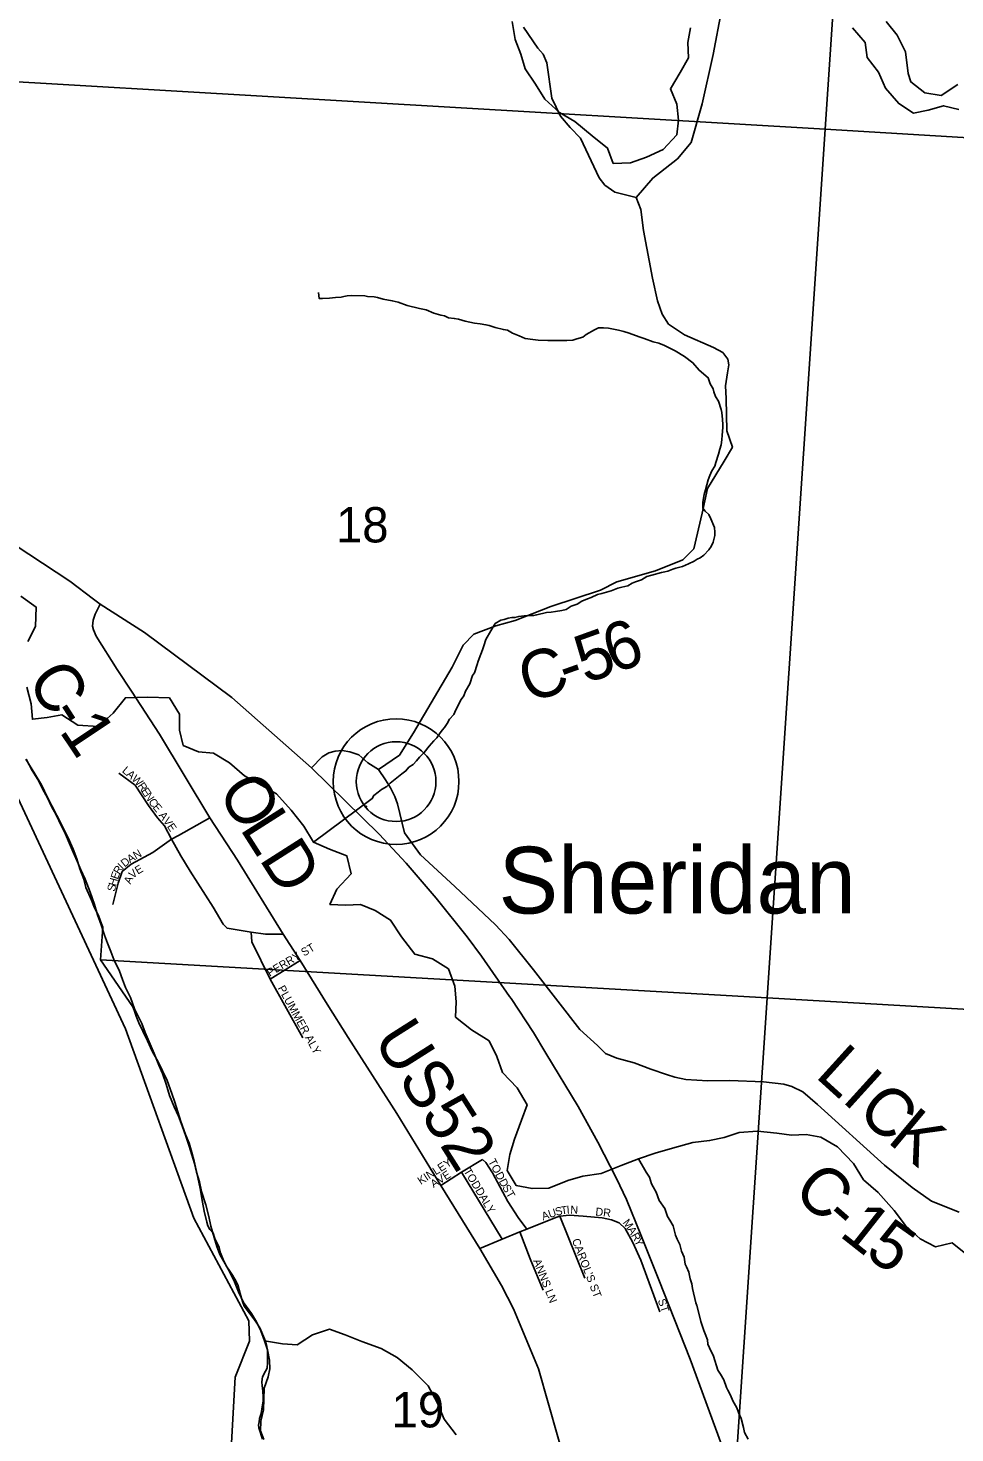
# Model space of a CAD drawing. Extents: x 0 to 34, y 0 to 22.
# Drawn here: x 2.788 to 3.885, y 18.575 to 20.238 of the extents above; entities that cross this region are included whole.
import ezdxf

# ---------------------------------------------------------------- set-up
doc = ezdxf.new("R2010")
doc.units = 0
for name, color, linetype in [('GM_X_County', 7, 'Continuous'), ('GM_X_County_Road', 7, 'Continuous'), ('GM_X_County_Road_Text', 7, 'Continuous'), ('GM_X_Major_River', 7, 'Continuous'), ('GM_X_Minor_River', 7, 'Continuous'), ('GM_X_Section', 7, 'Continuous'), ('GM_X_Section_Text', 7, 'Continuous'), ('GM_X_Township', 7, 'Continuous'), ('GM_X_Township_Road', 7, 'Continuous'), ('GM_X_Township_Subdivision', 7, 'Continuous'), ('GM_X_Township_Subdivision_Text', 7, 'Continuous'), ('GM_X_Unincorporated', 7, 'Continuous'), ('GM_X_Unincorporated_Location', 7, 'Continuous'), ('GM_X_Unincorporated_Text', 7, 'Continuous'), ('GM_X_US_Route', 7, 'Continuous')]:
    doc.layers.add(name, color=color, linetype=linetype)

msp = doc.modelspace()

# ---------------------------------------------------------------- linework, layer by layer
at = {"layer": 'GM_X_County'}
msp.add_lwpolyline([(2.1084, 19.9847), (2.1924, 19.9434), (2.3283, 19.8444), (2.4127, 19.8011), (2.4676, 19.7415), (2.5455, 19.6755), (2.6288, 19.5943), (2.748, 19.3841), (2.9028, 19.0532), (2.9838, 18.8289), (3.0489, 18.7074), (3.0497, 18.6835), (3.0326, 18.641), (3.0273, 18.5491)], dxfattribs=at)
at = {"layer": 'GM_X_County_Road'}
for points in [[(3.2021, 19.3601), (3.2271, 19.377), (3.2437, 19.4034), (3.2893, 19.4814), (3.3023, 19.5074), (3.3153, 19.5204), (3.3413, 19.5302), (3.3641, 19.5367), (3.4064, 19.5529), (3.4649, 19.5724), (3.4845, 19.5822), (3.53, 19.5952), (3.5625, 19.6082), (3.5755, 19.6212), (3.5853, 19.6635), (3.5918, 19.6927), (3.6113, 19.7253), (3.6211, 19.7415), (3.6146, 19.761), (3.6136, 19.7993), (3.613, 19.8141), (3.6155, 19.8295), (3.6171, 19.8393), (3.6158, 19.8459), (3.6099, 19.8537), (3.5989, 19.8597), (3.5643, 19.8748), (3.5454, 19.8874), (3.5379, 19.899), (3.5325, 19.9147), (3.5266, 19.9417), (3.5159, 19.9983), (3.5127, 20.0232), (3.5072, 20.0374), (3.5268, 20.0602), (3.556, 20.083), (3.5723, 20.1025), (3.5853, 20.148), (3.5983, 20.2065), (3.6081, 20.2586)], [(3.8033, 20.2455), (3.8163, 20.2293), (3.826, 20.2098), (3.8293, 20.1838), (3.8325, 20.174), (3.8488, 20.161), (3.8683, 20.1578), (3.8878, 20.1708)], [(2.8728, 19.5558), (2.8669, 19.5439), (2.8644, 19.537), (2.8639, 19.5299), (2.8651, 19.5255), (2.8681, 19.518), (2.8931, 19.4787), (2.9099, 19.453)], [(2.9099, 19.453), (2.9432, 19.4019), (3.0028, 19.303), (3.0355, 19.253), (3.0893, 19.1654), (3.1095, 19.1339), (3.1414, 19.0822), (3.1662, 19.0428), (3.224, 18.953), (3.2762, 18.8678), (3.3224, 18.7932), (3.3479, 18.7494), (3.3619, 18.7216), (3.3918, 18.6508), (3.426, 18.5298)], [(3.1231, 19.362), (3.1354, 19.3753), (3.1433, 19.3797), (3.1509, 19.3819), (3.1592, 19.3827), (3.1685, 19.3812), (3.1788, 19.3775), (3.1898, 19.3682), (3.2021, 19.3601), (3.2107, 19.3479), (3.2163, 19.3385), (3.2215, 19.328), (3.2249, 19.3197), (3.2332, 19.2851), (3.2518, 19.2592), (3.2926, 19.2215), (3.3407, 19.1763), (3.357, 19.1588), (3.3856, 19.123), (3.4405, 19.0523), (3.4616, 19.0335), (3.4708, 19.024), (3.4843, 19.0184), (3.5047, 19.0128), (3.5248, 19.0054), (3.5431, 18.9991), (3.553, 18.996), (3.5661, 18.9934), (3.5921, 18.9916), (3.6182, 18.9921), (3.6578, 18.9904), (3.6819, 18.9878), (3.6916, 18.9849), (3.7046, 18.9786), (3.7219, 18.9638), (3.8012, 18.8917), (3.8339, 18.8655), (3.8568, 18.8491), (3.8896, 18.836)]]:
    msp.add_lwpolyline(points, dxfattribs=at)
at = {"layer": 'GM_X_Major_River'}
for points in [[(2.8856, 19.1447), (2.8815, 19.1546), (2.8781, 19.1641), (2.8739, 19.1762), (2.8698, 19.188), (2.866, 19.2005), (2.8611, 19.2149), (2.855, 19.2305), (2.8501, 19.2415), (2.8456, 19.2517), (2.8407, 19.2623), (2.8361, 19.2733), (2.8316, 19.2836), (2.8267, 19.2938), (2.8206, 19.3063), (2.8153, 19.3162), (2.8104, 19.3268), (2.8044, 19.3371), (2.8002, 19.3465), (2.7923, 19.3591), (2.7851, 19.3723)], [(3.0666, 18.5669), (3.0625, 18.5775), (3.0628, 18.5889), (3.0662, 18.6022), (3.067, 18.628), (3.0715, 18.6413), (3.0738, 18.6507), (3.0731, 18.661), (3.0708, 18.6731), (3.0674, 18.6838), (3.0629, 18.6959), (3.0579, 18.7065), (3.0519, 18.7164), (3.0425, 18.7293), (3.0364, 18.7418), (3.0319, 18.7536), (3.0262, 18.765), (3.0209, 18.7752), (3.0145, 18.7862), (3.0111, 18.7957), (3.0077, 18.8063), (3.0039, 18.8196), (3.0013, 18.831), (2.9979, 18.845), (2.9929, 18.8606), (2.9903, 18.872), (2.9869, 18.8837), (2.9843, 18.8936), (2.9812, 18.9042), (2.9782, 18.9144), (2.9744, 18.9262), (2.9703, 18.9372), (2.9654, 18.9497), (2.9605, 18.9607), (2.9548, 18.9744), (2.951, 18.9877), (2.9465, 19.0002), (2.9423, 19.0101), (2.9366, 19.0241), (2.9321, 19.0351), (2.9261, 19.0487), (2.9223, 19.0594), (2.9136, 19.0768), (2.9087, 19.0901), (2.9026, 19.1022), (2.8992, 19.1117), (2.8955, 19.1216), (2.889, 19.1352), (2.8856, 19.1447)]]:
    msp.add_lwpolyline(points, dxfattribs=at)
at = {"layer": 'GM_X_Minor_River'}
for points in [[(3.3603, 20.2457), (3.364, 20.2244), (3.3708, 20.2069), (3.376, 20.1894), (3.388, 20.1712), (3.3993, 20.1537), (3.4167, 20.1377), (3.4348, 20.127), (3.4552, 20.1102), (3.4733, 20.0957), (3.4801, 20.0775), (3.5005, 20.0782), (3.5195, 20.0849), (3.5392, 20.094), (3.5552, 20.1114), (3.5575, 20.1288), (3.5553, 20.1478), (3.5478, 20.166), (3.5593, 20.185), (3.5692, 20.2024), (3.5685, 20.2206), (3.5716, 20.2381)], [(3.7632, 20.2381), (3.7783, 20.2206), (3.7805, 20.2031), (3.7941, 20.1856), (3.8023, 20.1666), (3.8181, 20.1483), (3.8355, 20.1369), (3.8529, 20.1406), (3.8711, 20.1459), (3.8893, 20.1412)], [(3.5861, 19.6695), (3.5862, 19.6763), (3.5871, 19.6812), (3.5879, 19.6858), (3.5892, 19.6911), (3.5924, 19.7032), (3.5944, 19.7081), (3.5967, 19.7137), (3.6003, 19.719), (3.6015, 19.7235), (3.6047, 19.7333), (3.6063, 19.7394), (3.6079, 19.7443), (3.6088, 19.7504), (3.6092, 19.756), (3.6098, 19.7651), (3.6098, 19.7686), (3.6096, 19.7743), (3.6086, 19.7826), (3.6079, 19.7864), (3.6046, 19.796), (3.6013, 19.8017), (3.5992, 19.8071), (3.5985, 19.8109), (3.5948, 19.8167), (3.5923, 19.8239), (3.5818, 19.8328), (3.5744, 19.8417), (3.5643, 19.8491), (3.5534, 19.8557), (3.5407, 19.862), (3.5339, 19.8648), (3.5275, 19.8664), (3.5169, 19.8704), (3.5109, 19.8724), (3.4989, 19.8768), (3.4925, 19.8784), (3.4864, 19.88), (3.4744, 19.8825), (3.4687, 19.883), (3.4626, 19.8831), (3.458, 19.8805), (3.4481, 19.875), (3.4442, 19.872), (3.437, 19.8698), (3.4321, 19.8684), (3.4252, 19.8678), (3.4188, 19.8679), (3.4025, 19.8678), (3.3912, 19.8683), (3.3851, 19.8692), (3.3757, 19.8705), (3.3689, 19.8733), (3.361, 19.8765), (3.355, 19.88), (3.3501, 19.8808), (3.3403, 19.8833), (3.3331, 19.8857), (3.3294, 19.8865), (3.3226, 19.8877), (3.3158, 19.8886), (3.3048, 19.8907), (3.2969, 19.8931), (3.292, 19.894), (3.2852, 19.8948), (3.2803, 19.8972), (3.2762, 19.898), (3.2679, 19.9001), (3.2585, 19.9044), (3.2509, 19.906), (3.2362, 19.9093), (3.2257, 19.9133), (3.2185, 19.9149), (3.2079, 19.917), (3.2011, 19.919), (3.197, 19.9195), (3.1894, 19.92), (3.186, 19.9208), (3.1705, 19.9211), (3.1652, 19.9208), (3.1614, 19.9201), (3.158, 19.9194), (3.1515, 19.9187), (3.1443, 19.9181), (3.136, 19.9175), (3.1322, 19.9176), (3.1312, 19.9248)], [(3.1254, 19.2742), (3.1949, 19.3257), (3.1968, 19.3294), (3.2018, 19.3335), (3.206, 19.3365), (3.2122, 19.3402), (3.216, 19.3439), (3.2241, 19.3502), (3.2298, 19.3551), (3.2348, 19.3584), (3.2383, 19.3629), (3.2433, 19.3662), (3.2472, 19.3703), (3.2506, 19.3748), (3.2564, 19.3804), (3.2622, 19.3879), (3.2676, 19.3939), (3.2715, 19.3976), (3.2746, 19.4025), (3.2777, 19.4067), (3.2804, 19.41), (3.2835, 19.4145), (3.2863, 19.4198), (3.2913, 19.4254), (3.2937, 19.4307), (3.3003, 19.4431), (3.3034, 19.4472), (3.3054, 19.4529), (3.3105, 19.4615), (3.3137, 19.4714), (3.3157, 19.4747), (3.3192, 19.4845), (3.3204, 19.4883), (3.3232, 19.4966), (3.3252, 19.5019), (3.3268, 19.5064), (3.3292, 19.514), (3.3351, 19.5241), (3.3402, 19.5328), (3.3471, 19.5369), (3.3509, 19.5375), (3.3558, 19.5394), (3.36, 19.54), (3.3638, 19.54), (3.3683, 19.5414), (3.3748, 19.5421), (3.3801, 19.5424), (3.3858, 19.5423), (3.3896, 19.5433), (3.401, 19.5458), (3.4067, 19.5465), (3.4116, 19.5471), (3.4192, 19.5482), (3.4245, 19.5496), (3.4303, 19.5533), (3.4375, 19.5558), (3.4429, 19.5595), (3.4498, 19.5621), (3.454, 19.5639), (3.4616, 19.5672), (3.4665, 19.5686), (3.4776, 19.5715), (3.4856, 19.5747), (3.4902, 19.5758), (3.4974, 19.5776), (3.5027, 19.5809), (3.5066, 19.5824), (3.5134, 19.5845), (3.5199, 19.5886), (3.5256, 19.59), (3.5371, 19.5932), (3.5412, 19.5943), (3.5447, 19.595), (3.5508, 19.5972), (3.5542, 19.5986), (3.5622, 19.6004), (3.5691, 19.6037), (3.5759, 19.6066), (3.5794, 19.6092), (3.5832, 19.6107), (3.5874, 19.614), (3.5932, 19.62), (3.5959, 19.6241), (3.5983, 19.6294), (3.6003, 19.637), (3.6004, 19.6411), (3.6001, 19.6465), (3.5957, 19.6568), (3.5932, 19.6618), (3.5891, 19.666), (3.5861, 19.6695)], [(2.7789, 19.5654), (2.797, 19.5524), (2.7961, 19.5296), (2.787, 19.5115)], [(2.786, 19.4576), (2.7912, 19.4378), (2.7926, 19.4196), (2.8101, 19.4218), (2.8275, 19.4248), (2.8464, 19.4126), (2.8706, 19.411), (2.8881, 19.4268), (2.9026, 19.445), (2.9291, 19.4457), (2.9548, 19.4448), (2.9669, 19.4258), (2.9668, 19.4068), (2.9712, 19.3886), (2.9894, 19.3809), (3.0068, 19.3793), (3.0257, 19.3679), (3.0438, 19.3526), (3.0642, 19.3412), (3.0816, 19.3312), (3.0989, 19.3122), (3.114, 19.2931), (3.1253, 19.2741), (3.1442, 19.2657), (3.1646, 19.258), (3.1698, 19.2368), (3.1531, 19.2186), (3.1447, 19.2004), (3.1636, 19.1996), (3.181, 19.2003), (3.1984, 19.1934), (3.2165, 19.1819), (3.2293, 19.1621), (3.2451, 19.1416), (3.2663, 19.1362), (3.2852, 19.124), (3.2927, 19.1035), (3.2941, 19.0852), (3.2933, 19.067), (3.3122, 19.0518), (3.3333, 19.0388), (3.3423, 19.0205), (3.3491, 19.0015), (3.3664, 18.9832), (3.3784, 18.9634), (3.3715, 18.9452), (3.3631, 18.9225), (3.3577, 18.9043), (3.3546, 18.8853), (3.3652, 18.8678), (3.3841, 18.864), (3.4038, 18.8646), (3.4265, 18.8737), (3.444, 18.8789), (3.466, 18.8819), (3.4895, 18.8916), (3.51, 18.8992), (3.5297, 18.9059), (3.5501, 18.9119), (3.5744, 18.9187), (3.5941, 18.9209), (3.6115, 18.9246), (3.629, 18.9306), (3.651, 18.932), (3.6737, 18.9297), (3.6911, 18.9273), (3.7085, 18.928), (3.7259, 18.9249), (3.7455, 18.9135), (3.7644, 18.8937), (3.7764, 18.8746), (3.7938, 18.8594), (3.8126, 18.838), (3.8262, 18.8205), (3.8436, 18.8045), (3.8617, 18.7953), (3.8814, 18.7998), (3.8995, 18.7853)], [(3.1865, 19.3148), (3.1886, 19.317)], [(3.51, 18.8992), (3.5189, 18.8834), (3.5229, 18.8777), (3.5254, 18.8696), (3.5273, 18.8662), (3.531, 18.8597), (3.5346, 18.8501), (3.5412, 18.8405), (3.5445, 18.831), (3.547, 18.8267), (3.5511, 18.8198), (3.5539, 18.8088), (3.5557, 18.8042), (3.559, 18.798), (3.5608, 18.79), (3.5641, 18.7828), (3.5654, 18.7748), (3.5669, 18.7713), (3.5694, 18.7652), (3.5712, 18.7572), (3.573, 18.7515), (3.574, 18.7457), (3.5779, 18.729), (3.579, 18.7255), (3.5825, 18.7118), (3.5839, 18.7068), (3.5875, 18.6961), (3.589, 18.6923), (3.5915, 18.6851), (3.5922, 18.6801), (3.594, 18.6755), (3.5988, 18.6659), (3.6041, 18.6491), (3.6071, 18.6445), (3.6111, 18.6376), (3.614, 18.6288), (3.6158, 18.6254), (3.6191, 18.6196), (3.6217, 18.6127), (3.6265, 18.6047), (3.6283, 18.599), (3.6315, 18.5921), (3.6344, 18.5814), (3.6354, 18.5753), (3.6398, 18.5676)], [(3.0674, 18.6838), (3.0887, 18.6805), (3.1061, 18.679), (3.1243, 18.691), (3.1441, 18.6978), (3.163, 18.6909), (3.1826, 18.6832), (3.2053, 18.6748), (3.2242, 18.6641), (3.2423, 18.6496), (3.2612, 18.6305), (3.2717, 18.6108), (3.2799, 18.591), (3.2943, 18.5727)]]:
    msp.add_lwpolyline(points, dxfattribs=at)
at = {"layer": 'GM_X_Section'}
for points in [[(2.6675, 20.8908), (2.6266, 20.1828), (3.731, 20.118), (3.7825, 20.8908)], [(3.7825, 20.8908), (3.731, 20.118), (4.8149, 20.0525), (4.8624, 20.8908)], [(2.6266, 20.1828), (3.731, 20.118), (3.6625, 19.0898), (2.8733, 19.1347), (2.876, 19.1737), (2.8734, 19.1805), (2.8707, 19.1873), (2.8662, 19.1964), (2.8624, 19.2055), (2.856, 19.2203), (2.8533, 19.2302), (2.8488, 19.2427), (2.845, 19.2544), (2.8408, 19.2658), (2.8348, 19.2794), (2.8276, 19.2942), (2.8155, 19.3173), (2.8068, 19.3344), (2.8034, 19.3419), (2.7954, 19.3552), (2.7848, 19.3723)], [(3.065, 18.5674), (3.0605, 18.581), (3.0601, 18.584), (3.0609, 18.5878), (3.0613, 18.592), (3.0632, 18.5977), (3.0647, 18.6056), (3.0658, 18.6124), (3.0658, 18.617), (3.0655, 18.6246), (3.0647, 18.6306), (3.0643, 18.6352), (3.0651, 18.6412), (3.0685, 18.6481), (3.0704, 18.6515), (3.0708, 18.6579), (3.0708, 18.6651), (3.0708, 18.6723), (3.07, 18.6772), (3.0689, 18.6814), (3.0674, 18.6863), (3.0617, 18.6992), (3.0575, 18.706), (3.0523, 18.7132), (3.047, 18.7201), (3.0432, 18.725), (3.0413, 18.7303), (3.0386, 18.7398), (3.0356, 18.75), (3.0322, 18.7568), (3.0296, 18.7617), (3.0261, 18.7663), (3.0227, 18.7716), (3.019, 18.778), (3.0152, 18.7879), (3.0137, 18.7943), (3.0084, 18.805), (3.0065, 18.8114), (3.0027, 18.8156), (3.0004, 18.8201), (2.9989, 18.8243), (2.9959, 18.8372), (2.994, 18.8482), (2.991, 18.8641), (2.9876, 18.8807), (2.9842, 18.8967), (2.9815, 18.9069), (2.9781, 18.9179), (2.974, 18.9281), (2.9683, 18.9433), (2.9611, 18.9664), (2.9577, 18.9766), (2.952, 18.9922), (2.9464, 19.0035), (2.9418, 19.0134), (2.9343, 19.0266), (2.929, 19.0388), (2.9233, 19.0505), (2.9184, 19.0604), (2.9153, 19.068), (2.9131, 19.0751), (2.9116, 19.0793), (2.8733, 19.1347), (3.6625, 19.0898), (3.5959, 18.098)]]:
    msp.add_lwpolyline(points, dxfattribs=at)
for points in [[(4.8149, 20.0525), (4.754, 19.0266), (3.6625, 19.0898), (3.731, 20.118)], [(3.6625, 19.0898), (4.754, 19.0266), (4.6942, 18.026), (3.5959, 18.098)]]:
    msp.add_lwpolyline(points, close=True, dxfattribs=at)
at = {"layer": 'GM_X_Township'}
msp.add_lwpolyline([(2.1084, 19.9847), (2.1924, 19.9434), (2.3283, 19.8444), (2.4127, 19.8011), (2.4676, 19.7415), (2.5455, 19.6755), (2.6288, 19.5943), (2.748, 19.3841), (2.9028, 19.0532), (2.9838, 18.8289), (3.0489, 18.7074), (3.0497, 18.6835), (3.0326, 18.641), (3.0273, 18.5491)], dxfattribs=at)
at = {"layer": 'GM_X_Township_Road'}
msp.add_lwpolyline([(3.3737, 20.2388), (3.3908, 20.2141), (3.3972, 20.2069), (3.4014, 20.1967), (3.4074, 20.1549), (3.4176, 20.1336), (3.429, 20.12), (3.4415, 20.1075), (3.4634, 20.0604), (3.4703, 20.052), (3.482, 20.0437), (3.5072, 20.0374)], dxfattribs=at)
at = {"layer": 'GM_X_Township_Subdivision'}
for points in [[(2.8951, 19.356), (2.9142, 19.3416), (2.9299, 19.3174), (2.9408, 19.303), (2.9489, 19.2935), (2.9574, 19.2776), (2.9682, 19.2579), (2.9792, 19.2399), (3.0065, 19.1973), (3.0184, 19.1771), (3.023, 19.1723), (3.0517, 19.1677), (3.0684, 19.1651), (3.0893, 19.1654)], [(3.0028, 19.303), (2.9655, 19.2821)], [(2.9655, 19.2821), (2.9574, 19.2776), (2.935, 19.262), (2.9095, 19.2482), (2.8988, 19.2393), (2.8943, 19.2255), (2.888, 19.2005)], [(3.0517, 19.1677), (3.0522, 19.1561), (3.074, 19.112), (3.1126, 19.0424)], [(3.074, 19.112), (3.1095, 19.1339)], [(3.2762, 18.8678), (3.3006, 18.8834), (3.3252, 18.8987)], [(3.3252, 18.8987), (3.3292, 18.895), (3.3371, 18.8829), (3.3554, 18.8488), (3.3677, 18.8297), (3.378, 18.8162)], [(3.3006, 18.8834), (3.3485, 18.8042)], [(3.3224, 18.7932), (3.3485, 18.8042), (3.3696, 18.8128), (3.378, 18.8162), (3.4122, 18.8297), (3.4169, 18.8315), (3.4282, 18.8327), (3.4447, 18.8313), (3.4669, 18.8296), (3.478, 18.8272)], [(3.4169, 18.8315), (3.4463, 18.7581)], [(3.478, 18.8272), (3.4871, 18.8237), (3.4944, 18.8167), (3.5035, 18.8003), (3.5126, 18.7792), (3.5352, 18.7181)], [(3.3696, 18.8128), (3.3816, 18.7808), (3.3972, 18.7439)]]:
    msp.add_lwpolyline(points, dxfattribs=at)
at = {"layer": 'GM_X_Unincorporated'}
for radius in [0.0744, 0.0472]:
    msp.add_circle((3.2231, 19.3458), radius, dxfattribs=at)
at = {"layer": 'GM_X_Unincorporated_Location'}
msp.add_line((3.2231, 19.3458), (3.2231, 19.3458), dxfattribs=at)
at = {"layer": 'GM_X_US_Route'}
for points in [[(2.1084, 20.078), (2.1384, 20.0579), (2.2967, 19.9448), (2.4906, 19.8092), (2.7221, 19.6584), (2.837, 19.5832), (2.8649, 19.5619)], [(2.8649, 19.5619), (2.8728, 19.5558), (2.9252, 19.5223), (3.0287, 19.4452), (3.1231, 19.362), (3.2031, 19.2836), (3.2351, 19.2494), (3.2704, 19.2077), (3.3072, 19.1621), (3.3243, 19.139), (3.3575, 19.0915)], [(3.3575, 19.0915), (3.3594, 19.0889), (3.3856, 19.0487), (3.4004, 19.0243)], [(3.4004, 19.0243), (3.4386, 18.9612), (3.4619, 18.9191), (3.484, 18.876), (3.4957, 18.851), (3.5126, 18.8094), (3.5341, 18.7561), (3.5713, 18.6622), (3.654, 18.4363), (3.7163, 18.2698), (3.7496, 18.1784)]]:
    msp.add_lwpolyline(points, dxfattribs=at)

# ---------------------------------------------------------------- texts
at = {"layer": 'GM_X_County_Road_Text'}
for s, height, rotation, p in [('6', 0.0568, 19.8238, (3.4803, 19.4732)), ('5', 0.0568, 19.7675, (3.4473, 19.4614)), ('C', 0.0568, 18.2134, (3.3794, 19.4384)), ('C', 0.0568, 302.372, (2.7851, 19.4661)), ('-', 0.0568, 19.6378, (3.4252, 19.4535)), ('1', 0.0568, 303.7976, (2.8236, 19.4057)), ('-', 0.0568, 302.7063, (2.8103, 19.4264)), ('O', 0.0568, 301.0729, (3.0108, 19.3344)), ('L', 0.0568, 302.4533, (3.0374, 19.2903)), ('D', 0.0568, 302.5044, (3.0602, 19.2544)), ('US52', 0.05682, 302.3564, (3.1949, 19.0409)), ('L', 0.0568, 317.8303, (3.7179, 18.9969)), ('I', 0.0568, 317.8278, (3.7494, 18.9683)), ('C', 0.0568, 317.9398, (3.7668, 18.9526)), ('K', 0.0568, 320.1175, (3.8032, 18.9198)), ('C', 0.0568, 317.4459, (3.6908, 18.8588)), ('-', 0.0568, 318.8513, (3.7263, 18.8262)), ('1', 0.0568, 321.7372, (3.7463, 18.8089)), ('5', 0.0568, 324.7667, (3.7764, 18.7853))]:
    msp.add_text(s, height=height, rotation=rotation, dxfattribs=at).set_placement(p)
at = {"layer": 'GM_X_Section_Text'}
for s, p in [('18', (3.1519, 19.6289)), ('19', (3.2177, 18.5814))]:
    msp.add_text(s, height=0.04186, rotation=0, dxfattribs=at).set_placement(p)
at = {"layer": 'GM_X_Township_Subdivision_Text'}
for s, rotation, p in [('L', 319.2176, (2.898, 19.3577)), ('A', 319.2171, (2.9031, 19.3534)), ('W', 315.3938, (2.9093, 19.3481)), ('R', 304.5792, (2.9167, 19.3408)), ('E', 303.3207, (2.9209, 19.3347)), ('N', 303.3436, (2.9246, 19.3291)), ('C', 306.1556, (2.9294, 19.3217)), ('E', 309.7107, (2.9343, 19.3152)), ('A', 307.4786, (2.9416, 19.3058)), ('V', 306.1174, (2.9467, 19.2992)), ('E', 303.9401, (2.9515, 19.2926)), ('A', 31.7969, (2.9081, 19.249)), ('N', 29.7757, (2.9151, 19.2534)), ('E', 70.9354, (2.8938, 19.2294)), ('R', 59.2866, (2.8957, 19.2352)), ('I', 45.3593, (2.8992, 19.2412)), ('D', 39.0122, (2.9019, 19.244)), ('V', 41.0831, (2.9115, 19.2304)), ('E', 31.1019, (2.9174, 19.2356)), ('S', 76.8807, (2.8901, 19.2151)), ('H', 74.7835, (2.8916, 19.2215)), ('A', 65.4073, (2.9087, 19.2237)), ('PERRY ST', 30.6503, (3.0735, 19.1146)), ('PLUMMER ALY', 298.8353, (3.0826, 19.1014)), ('KINLEY', 32.8004, (3.2523, 18.8683)), ('TODD', 297.899, (3.3318, 18.8964)), ('AVE', 32.6173, (3.2675, 18.8646)), ('TODD', 301.219, (3.3026, 18.8848)), ('ST', 299.7432, (3.3484, 18.8656)), ('ALY', 300.9626, (3.3209, 18.854)), ('U', 18.5965, (3.405, 18.829)), ('S', 14.9673, (3.4127, 18.8317)), ('T', 8.2262, (3.4189, 18.8333)), ('I', 4.4951, (3.4253, 18.8343)), ('N', 357.0781, (3.4292, 18.8346)), ('DR', 353.9898, (3.4587, 18.8323)), ('A', 18.5965, (3.3971, 18.8264)), ('M', 307.7979, (3.4907, 18.8235)), ('A', 300.9188, (3.4966, 18.8158)), ('R', 299.3382, (3.5009, 18.8087)), ("CAROL'S ST", 291.2504, (3.431, 18.8029)), ('Y', 295.8479, (3.5045, 18.8023)), ('ANNS LN', 291.4506, (3.3852, 18.7787)), ('ST', 288.4382, (3.5327, 18.7319))]:
    msp.add_text(s, height=0.00947, rotation=rotation, dxfattribs=at).set_placement(p)
at = {"layer": 'GM_X_Unincorporated_Text'}
msp.add_text('Sheridan', height=0.07898, rotation=0, dxfattribs=at).set_placement((3.3444, 19.1897))

doc.saveas('drawing.dxf')
